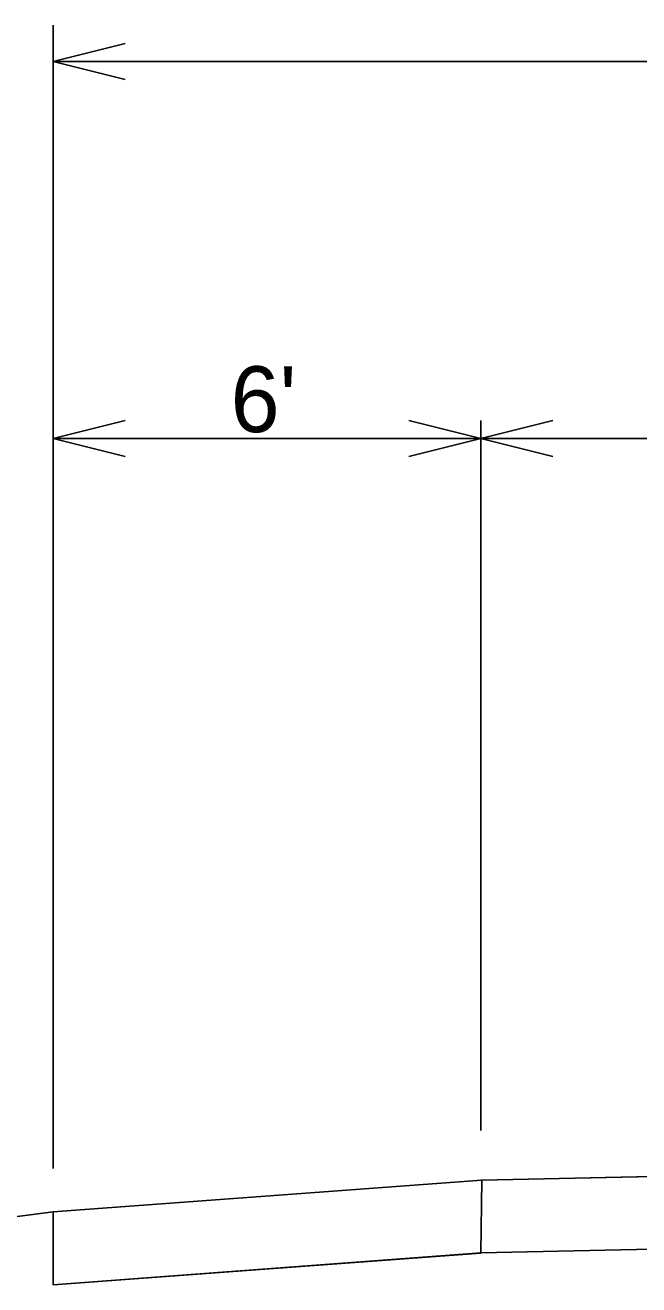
# Model space of a CAD drawing. Extents: x 10133 to 81668, y 4856 to 11018.
# Drawn here: x 10585.5 to 10725.2, y 5413.2 to 5700.3 of the extents above; entities that cross this region are included whole.
import ezdxf

# ---------------------------------------------------------------- set-up
doc = ezdxf.new("R2010")
doc.units = 0
for name, color, linetype in [('dsnXsPCCPavementBottom', 7, 'Continuous'), ('dsnXsShldrEarthFill', 7, 'Continuous'), ('dsnXsShldrGranular', 7, 'Continuous'), ('dsnXsShldrGranularBottom', 7, 'Continuous'), ('dsnXsShldrSpecialBackBottom', 7, 'Continuous')]:
    doc.layers.add(name, color=color, linetype=linetype)

msp = doc.modelspace()

# ---------------------------------------------------------------- linework, layer by layer
at = {"layer": 'dsnXsPCCPavementBottom'}
for p, q in [((10591.83, 5439.73), (10591.83, 5700.35)), ((11184.03, 5692.07), (10591.83, 5692.07)), ((10689.23, 5610.22), (10689.23, 5448.35)), ((10689.23, 5606.12), (10591.83, 5606.12)), ((10888.15, 5606.12), (10689.47, 5606.12))]:
    msp.add_line(p, q, dxfattribs=at)
for points in [[(10608.22, 5687.97), (10591.83, 5692.07), (10608.22, 5696.17)], [(10608.22, 5610.22), (10591.83, 5606.12), (10608.22, 5602.02)], [(10672.84, 5602.02), (10689.23, 5606.12), (10672.84, 5610.22)], [(10705.62, 5610.22), (10689.23, 5606.12), (10705.62, 5602.02)]]:
    msp.add_lwpolyline(points, dxfattribs=at)
at = {"layer": 'dsnXsShldrGranular'}
msp.add_line((10888.26, 5424.75), (10689.23, 5420.52), dxfattribs=at)
msp.add_lwpolyline([(10689.23, 5420.52), (10689.47, 5437.08), (10887.91, 5441.3)], dxfattribs=at)
msp.add_lwpolyline([(10591.83, 5429.81), (10689.47, 5437.08), (10689.23, 5420.52), (10591.83, 5413.21)], close=True, dxfattribs=at)
at = {"layer": 'dsnXsShldrGranularBottom'}
for p, q in [((10887.91, 5441.3), (10689.47, 5437.08)), ((10689.47, 5437.08), (10689.23, 5420.52)), ((10591.83, 5429.81), (10468.72, 5414.34)), ((10689.23, 5420.52), (10888.26, 5424.75))]:
    msp.add_line(p, q, dxfattribs=at)
at = {"layer": 'dsnXsShldrSpecialBackBottom'}
for p, q in [((10689.47, 5437.08), (10591.83, 5429.81)), ((10591.83, 5429.81), (10591.83, 5413.21)), ((10689.23, 5420.46), (10591.83, 5413.21))]:
    msp.add_line(p, q, dxfattribs=at)

# ---------------------------------------------------------------- texts
at = {"layer": 'dsnXsShldrEarthFill'}
msp.add_text("6'", height=15, rotation=360, dxfattribs=at).set_placement((10632.26, 5607.59))

doc.saveas('drawing.dxf')
